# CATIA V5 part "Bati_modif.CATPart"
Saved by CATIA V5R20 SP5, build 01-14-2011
Part number: Bati
Publications: "Corps principal"
Bounding box of the stored display mesh (mm): x -17.479 to 17.479, y -15.2 to 72.3, z -21.828 to 5.5
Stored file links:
  J:\IAO\Bati_modif.CATPart
  J:\Projet\CAO\Projet IAO.CATProduct
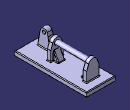
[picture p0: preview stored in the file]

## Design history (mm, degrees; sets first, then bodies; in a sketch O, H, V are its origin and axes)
External parameters (linked from other documents)
  `External.Diamètre coulisseau` = 10 mm
  `External.Epaisseur pivot` = 2 mm
  External.AB = 10 mm
  `External.Diamètre pivot` = 4 mm
  External.BC = 41 mm
  `External.Longueur axe pivot` = 6 mm
Set1
  Point1: type OnCurve, Support Line1, Ratio 0.5
  Line1: type PtPt, FirstPoint vertex [face of Pad3 from Sketch3.L1 | face of Pad3 from Sketch3.A1 | start face of Pad3], SecondPoint vertex [face of Pad2 from Sketch2.L2 | start face of Pad2 | face of Pad2 from Sketch2.A1]
  Plane1: type OffsetPt, RefPlane zx-plane, RefPoint Point1
Set2
  Line2: linked copy from another document
  Line3: linked copy from another document
Body1 (main body)
  Sketch1 on zx-plane, origin (0, 0, 0), H (-1, 0, 0), V (0, 0, 1)
    circle A1 centre (0, 0) radius 3
    point P1 (0, 0)
    radius A1 = 3 {= `External.Diamètre coulisseau` /2-`External.Epaisseur pivot`}
    coincidence: P1 O
  Pad1: profile Sketch1, direction (0, -1, 0), length -16.8 {= (-External.AB -`External.Diamètre pivot` )*1.20}, opposite side length 58.3 {= (External.AB +External.BC+`External.Diamètre pivot` /2 )*1.1}
  Sketch2 on start face of Pad1, origin (0, 58.3, 0), H (-1, 0, 0), V (0, 0, 1)
    arc A1 centre (0, 0) radius 5.5 from (5.2004, 1.7906) to (-5.2004, 1.7906) ccw
    point P1 (-5.2004, 1.7906)
    point P2 (5.2004, 1.7906)
    reference projected line E1 (0, 12) -> (0, 0) from Line2
    line L1 (5.2004, 1.7906) -> (7.4793, -4.828)
    line L2 (-5.2004, 1.7906) -> (-7.4793, -4.828)
    point P4 (-7.4793, -4.828)
    line L3 (-7.4793, -4.828) -> (-7.4793, -16.828)
    point P6 (-7.4793, -4.828)
    line L4 (7.4793, -4.828) -> (7.4793, -16.828)
    line L5 (7.4793, -16.828) -> (-7.4793, -16.828)
    length L2 = 7
    length L1 = 7 {= Sketch2.length(L2)}
    length L4 = 12 {= External.AB *1.2}
    radius A1 = 5.5
    angle L2 L1 = 38
    symmetry: P2 P1 E1
    tangency: L1 A1, L2 A1
    vertical: L4 V, L3 V
    coincidence: P6 P4
    horizontal: L5 H
  Pad2: profile Sketch2, direction (0, 1, 0), length 4
  Sketch3 on end face of Pad1, origin (0, 16.8, 0), H (1, 0, 0), V (0, 0, 1)
    point P1 (-5.2004, 1.7906)
    point P2 (5.2004, 1.7906)
    arc A1 centre (0, 0) radius 5.5 from (5.2004, 1.7906) to (-5.2004, 1.7906) ccw
    line L1 (5.2004, 1.7906) -> (7.4793, -4.828)
    point P5 (-7.4793, -4.828)
    line L2 (-5.2004, 1.7906) -> (-7.4793, -4.828)
    point P7 (-7.4793, -4.828)
    line L3 (-7.4793, -4.828) -> (-7.4793, -16.828)
    line L4 (7.4793, -4.828) -> (7.4793, -16.828)
    line L5 (7.4793, -16.828) -> (-7.4793, -16.828)
    reference projected point E1 (0, 0) from Line3
    reference projected line E2 (7.0085, -16.828) -> (-7.0085, -16.828) from edge [start face of Pad2 | face of Pad2 from Sketch2.L5]
    length L4 = 12 {= Sketch2.length(L4)}
    length L1 = 7 {= Sketch2.length(L2)}
    radius A1 = 5.5 {= Sketch2.radius(A1)}
    length L2 = 7 {= Sketch3.length(L1)}
    horizontal: L5 H
    vertical: L4 V, L3 V
    tangency: L2 A1, L1 A1
    concentricity: E1 A1
    symmetry: P2 P1 V
    coincidence: P7 P5, L5 E2
  Pad3: profile Sketch3, direction (0, -1, 0), length 2, opposite side length 2
  Sketch4 on face of Pad2 from Sketch2.L5, origin (0, 0, -16.828), H (1, 0, 0), V (0, -1, 0)
    line L1 (-17.4793, 15.2) -> (17.4793, 15.2)
    line L2 (17.4793, 15.2) -> (17.4793, -72.3)
    line L3 (17.4793, -72.3) -> (-17.4793, -72.3)
    line L4 (-17.4793, -72.3) -> (-17.4793, 15.2)
    reference projected line E1 (-7.4793, -21.55) -> (-7.4793, -17.55) from edge [face of Pad3 from Sketch3.L5 | face of Pad3 from Sketch3.L3]
    reference projected line E2 (7.4793, -21.55) -> (7.4793, -17.55) from edge [face of Pad3 from Sketch3.L4 | face of Pad3 from Sketch3.L5]
    reference projected line E3 (7.4793, -62.3) -> (-7.4793, -62.3) from edge [face of Pad2 from Sketch2.L5 | end face of Pad2]
    reference projected line E4 (-7.4793, -14.8) -> (7.4793, -14.8) from edge [face of Pad3 from Sketch3.L5 | end face of Pad3]
    distance L4 E1 = 10
    distance L2 E2 = 10
    distance L3 E3 = 10
    distance L1 E4 = 30
    horizontal: L1 H, L3 H
    vertical: L2 V, L4 V
  Pad4: profile Sketch4, direction (0, 0, -1), length 5
  Sketch5 on yz-plane, origin (0, 0, 0), H (0, 1, 0), V (0, 0, 1)
    arc A1 centre (0, 0) radius 4 from (3.7821, 1.3023) to (-3.7821, 1.3023) ccw
    point P1 (-3.7821, 1.3023)
    point P2 (3.7821, 1.3023)
    line L1 (-3.7821, 1.3023) -> (-5.0843, -2.4798)
    line L2 (3.7821, 1.3023) -> (5.0843, -2.4798)
    line L3 (5.0843, -2.4798) -> (7.3569, -16.828)
    line L4 (7.3569, -16.828) -> (-7.3569, -16.828)
    line L5 (-7.3569, -16.828) -> (-5.0843, -2.4798)
    reference intersected line E1 (-12.45, -16.828) -> (90.2, -16.828) from start face of Pad4
    arc A2 centre (0, 0) radius 2 from (0, -2) to (0, 2) ccw
    point P7 (0, -2)
    point P8 (0, 2)
    point P9 (0, 2)
    point P10 (0, -2)
    arc A3 centre (0, 0) radius 2 from (0, -2) to (0, 2) cw
    radius A1 = 4 {= `External.Diamètre pivot`}
    angle L1 L2 = 38
    length L1 = 4
    radius A2 = 2 {= `External.Diamètre pivot` /2}
    angle L3 L2 = 170
    tangency: L1 A1, L2 A1
    symmetry: P1 P2 V, P8 P9 V, P7 P10 V, A2 A3 V, L3 L5 V
    horizontal: L4 H
    coincidence: L4 E1, P7 V, P8 V
  Pad5: profile Sketch5, direction (1, 0, 0), length -3 {= -`External.Longueur axe pivot` /2}, opposite side length 9 {= `External.Longueur axe pivot` *1.5}
  Fillet1: radius 0.8, on start face of Pad4
  Sketch6 on yz-plane, origin (0, 0, 0), H (0, 1, 0), V (0, 0, 1)
    line L1 (59.5234, -3.9375) -> (59.5234, -19.4748)
    line L2 (59.5234, -19.4748) -> (50.8787, -19.4748)
    line L3 (50.8787, -19.4748) -> (59.5234, -3.9375)
    vertical: L1 V
    horizontal: L2 H
  Pad6: profile Sketch6, direction (1, 0, 0), length 4, mirrored extent
  Fillet2: radius 0.8, on end face of Pad6; face of Pad6 from Sketch6.L3; start face of Pad6
  Mirror1: of Pad6, Fillet2, about Plane1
